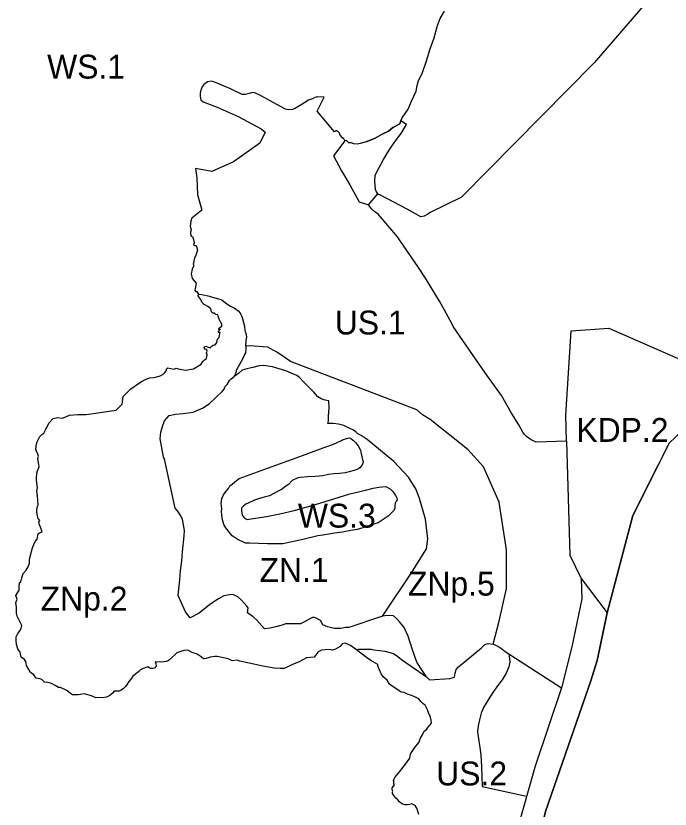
# Model space of a CAD drawing. Extents: x 7421614 to 7422630, y 5544623 to 5545754.
# Drawn here: x 7421918.2 to 7422192.7, y 5544838.1 to 5545170.9 of the extents above; entities that cross this region are included whole.
import ezdxf

# ---------------------------------------------------------------- set-up
doc = ezdxf.new("R2010")
doc.units = 0
for name, color, linetype in [('LIN_Granica Planu', 7, 'Continuous'), ('LIN_Linia Zabudowy Nieprzekraczalna', 7, 'Continuous'), ('LIN_Linie Rozgraniczajace', 7, 'Continuous'), ('TXT_Oznaczenia Przeznaczenia', 7, 'Continuous')]:
    doc.layers.add(name, color=color, linetype=linetype)

msp = doc.modelspace()

# ---------------------------------------------------------------- linework, layer by layer
at = {"layer": 'LIN_Granica Planu'}
for points in [[(7422208.14, 5545006.76), (7422192.24, 5544991.56), (7422177, 5544961.18), (7422166.21, 5544920.42)], [(7422166.21, 5544920.42), (7422162.02, 5544900.44), (7422159.37, 5544891.82), (7422140.37, 5544837.11), (7422136.08, 5544819.42), (7422134.53, 5544813.25), (7422129.23, 5544788.52), (7422123.65, 5544775.25), (7422118.35, 5544765.76), (7422111.44, 5544749.36), (7422109.16, 5544743.94), (7422108.81, 5544743.12)]]:
    msp.add_lwpolyline(points, dxfattribs=at)
at = {"layer": 'LIN_Linia Zabudowy Nieprzekraczalna'}
for p, q in [((7422079.22, 5545125.61), (7422076.29, 5545124.01)), ((7422079.75, 5545126.84), (7422079.22, 5545125.61)), ((7422074.45, 5545122.44), (7422071.78, 5545121.21)), ((7422076.29, 5545124.01), (7422074.45, 5545122.44)), ((7422056.19, 5545118.39), (7422051.48, 5545112.08)), ((7422068.85, 5545119.56), (7422065.13, 5545118.08)), ((7422071.78, 5545121.21), (7422068.85, 5545119.56)), ((7422066.17, 5545091.62), (7422070, 5545096.25)), ((7422062.26, 5545092.78), (7422066.17, 5545091.62))]:
    msp.add_line(p, q, dxfattribs=at)
for points in [[(7422070, 5545096.25), (7422069.43, 5545097.07), (7422069.11, 5545098.01), (7422068.71, 5545101.51), (7422068.97, 5545103.93), (7422069.56, 5545105.38), (7422072.39, 5545110.56), (7422074.1, 5545113.36), (7422075.3, 5545115.32), (7422077.49, 5545118.45), (7422079.84, 5545121.47), (7422082.09, 5545125.28), (7422079.75, 5545126.84)], [(7422065.13, 5545118.08), (7422062.61, 5545117.36), (7422061.5, 5545117.05), (7422060.03, 5545117.18), (7422058.87, 5545117.54), (7422057.88, 5545117.63), (7422056.82, 5545118.5), (7422056.19, 5545118.39)], [(7422051.48, 5545112.08), (7422054.82, 5545105.91), (7422058.35, 5545100), (7422062.26, 5545092.78)], [(7422124.98, 5544903.28), (7422125.37, 5544899.8), (7422124.97, 5544897.74), (7422123.82, 5544895.04), (7422122.14, 5544892.32), (7422120.59, 5544890.28), (7422118.51, 5544887.46), (7422117.06, 5544885.07), (7422114.4, 5544880.74), (7422113.44, 5544878.34), (7422112.62, 5544875.45), (7422112.07, 5544873.02), (7422111.88, 5544870.57), (7422112.09, 5544868.49), (7422112.78, 5544863.94), (7422113.24, 5544860.86), (7422113.53, 5544855.99), (7422113.74, 5544847.6), (7422132.46, 5544843.53)]]:
    msp.add_lwpolyline(points, dxfattribs=at)
at = {"layer": 'LIN_Linie Rozgraniczajace'}
for p, q in [((7422155.33, 5544934.86), (7422166.21, 5544920.42)), ((7422071.09, 5544918.7), (7422072.02, 5544918.95))]:
    msp.add_line(p, q, dxfattribs=at)
for points in [[(7422247.74, 5545302.11), (7422251.81, 5545292.57), (7422253.78, 5545282.38), (7422253.25, 5545272.02), (7422246.41, 5545262.11), (7422217.9, 5545236.43), (7422182.85, 5545176.71), (7422160.75, 5545151.12), (7422105.13, 5545094.82), (7422092.03, 5545088.33), (7422090.99, 5545087.63), (7422089.52, 5545086.84), (7422088.09, 5545086.6), (7422082.36, 5545089.7), (7422070.87, 5545095.79), (7422070, 5545096.25)], [(7422080.29, 5545128.07), (7422082.74, 5545131.73), (7422084.09, 5545135.14), (7422086.1, 5545139.3), (7422086.58, 5545141.7), (7422087.1, 5545143.77), (7422088.63, 5545146.68), (7422090.38, 5545151.56), (7422091.96, 5545156.97), (7422093.66, 5545161.66), (7422094.86, 5545166.45), (7422096.25, 5545169.76), (7422098.02, 5545172.85)], [(7422065.13, 5545118.08), (7422062.61, 5545117.36), (7422061.5, 5545117.05), (7422060.03, 5545117.18), (7422058.87, 5545117.54), (7422057.88, 5545117.63), (7422056.82, 5545118.5), (7422056.19, 5545118.39), (7422055.75, 5545119.31), (7422055.27, 5545119.74), (7422054.24, 5545120.84), (7422054.01, 5545121.66), (7422053.42, 5545122.18), (7422052.75, 5545122.65), (7422052.68, 5545122.73), (7422051.83, 5545122.15), (7422044.51, 5545130.94), (7422047.5, 5545136.72), (7422044.8, 5545136.91), (7422044.43, 5545136.75), (7422044.15, 5545136.74), (7422043.59, 5545136.63), (7422042.57, 5545136.08), (7422040.95, 5545135.5), (7422037.89, 5545133.5), (7422035.09, 5545131.87), (7422034.25, 5545131.59), (7422032.55, 5545131.4), (7422031.25, 5545131.71), (7422024.63, 5545135.31), (7422022.58, 5545136.46), (7422020.27, 5545137.66), (7422019.27, 5545138.21), (7422018.39, 5545138.57), (7422017.5, 5545138.68), (7422016.02, 5545138.32), (7422014.32, 5545137.81), (7422013.05, 5545137.85), (7422007.91, 5545140.35), (7422001.29, 5545143.24), (7422000.24, 5545143.5), (7421998.73, 5545143.12), (7421997.2, 5545142.19), (7421996.32, 5545141.04), (7421995.77, 5545139.75), (7421995.42, 5545138.46), (7421995.48, 5545136.96), (7421995.82, 5545135.62), (7421996.69, 5545134.81), (7422002.69, 5545132.49), (7422011.37, 5545128.68), (7422021.07, 5545123.48), (7422022.81, 5545122), (7422020.59, 5545117.39), (7422009.53, 5545109.65), (7422000.42, 5545105.58), (7421993.48, 5545106.8), (7421993.62, 5545105.84), (7421994.07, 5545102.87), (7421994.39, 5545095.94), (7421996.21, 5545089.35), (7421992.72, 5545086.5), (7421992.01, 5545085.92), (7421991.58, 5545084.82), (7421991.37, 5545083.67), (7421991.33, 5545082.65), (7421991.76, 5545081.08), (7421991.47, 5545080.17), (7421991.42, 5545079.37), (7421991.78, 5545078.48), (7421992.25, 5545078.24), (7421992.69, 5545077.03), (7421992.95, 5545075.67), (7421992.68, 5545074.93), (7421993.29, 5545074.47), (7421993.76, 5545074.52), (7421993.98, 5545074.03), (7421994.36, 5545072.54), (7421993.61, 5545070.44), (7421993.11, 5545069.18), (7421992.51, 5545066.64), (7421992.77, 5545066.16), (7421992.1, 5545064.59), (7421991.67, 5545062.61), (7421992.13, 5545060.7), (7421993.86, 5545058.68), (7421993.53, 5545057.03), (7421993.19, 5545055.79), (7421993.7, 5545055.12), (7421994, 5545055.37), (7421994.75, 5545054.14)], [(7422079.75, 5545126.84), (7422080.29, 5545128.07)], [(7422070, 5545096.25), (7422069.43, 5545097.07), (7422069.11, 5545098.01), (7422068.71, 5545101.51), (7422068.97, 5545103.93), (7422069.56, 5545105.38), (7422072.39, 5545110.56), (7422074.1, 5545113.36), (7422075.3, 5545115.32), (7422077.49, 5545118.45), (7422079.84, 5545121.47), (7422082.09, 5545125.28), (7422079.75, 5545126.84)], [(7422076.29, 5545124.01), (7422079.22, 5545125.61)], [(7422079.22, 5545125.61), (7422079.75, 5545126.84)], [(7422071.78, 5545121.21), (7422074.45, 5545122.44)], [(7422074.45, 5545122.44), (7422076.29, 5545124.01)], [(7422065.13, 5545118.08), (7422068.85, 5545119.56)], [(7422068.85, 5545119.56), (7422071.78, 5545121.21)], [(7422149.25, 5544992.43), (7422136.41, 5544992.07), (7422134.42, 5544992.99), (7422132.41, 5544994.44), (7422131.61, 5544995.27), (7422130.8, 5544996.2), (7422129.25, 5544999.3), (7422126.13, 5545004.12), (7422121.88, 5545011.57), (7422115, 5545021.11), (7422106.96, 5545032.85), (7422101.65, 5545040.58), (7422101.51, 5545040.82), (7422101.14, 5545041.85), (7422098.07, 5545047.34), (7422095.84, 5545051.15), (7422092, 5545057.53), (7422090.01, 5545060.83), (7422086.76, 5545065.72), (7422081.01, 5545074.23), (7422078.29, 5545078.1), (7422071.82, 5545085.72), (7422070.11, 5545087.66), (7422068.73, 5545088.64), (7422067.38, 5545089.95), (7422066.17, 5545091.62), (7422070, 5545096.25)], [(7422061.03, 5544904.84), (7422058.6, 5544906.67), (7422056.35, 5544907.7), (7422055.07, 5544907.36), (7422054.2, 5544906.26), (7422052.23, 5544905.19), (7422051.02, 5544904.79), (7422049.65, 5544905.06), (7422046.41, 5544904.79), (7422045.01, 5544904.03), (7422043.31, 5544901.78), (7422040.05, 5544901.53), (7422036.99, 5544899.83), (7422034.01, 5544898.62), (7422030.77, 5544897.05), (7422029.08, 5544896.99), (7422026.52, 5544897.21), (7422021.8, 5544898.01), (7422017.96, 5544898.9), (7422012.07, 5544900.11), (7422010.96, 5544900.53), (7422008.96, 5544900.29), (7422007.23, 5544901.04), (7422002.65, 5544902.08), (7422001.58, 5544902.14), (7421999.67, 5544901.74), (7421997.95, 5544901.31), (7421996.9, 5544901.17), (7421995.92, 5544902), (7421994.25, 5544903.05), (7421992.11, 5544903.83), (7421990.28, 5544904.7), (7421988.58, 5544904.58), (7421986.5, 5544903.96), (7421985.75, 5544903.65), (7421982.77, 5544900.8), (7421982.01, 5544900.28), (7421981.26, 5544900), (7421980.2, 5544899.82), (7421978.8, 5544899.7), (7421976.63, 5544899.88), (7421976.95, 5544899.09), (7421976.96, 5544898.03), (7421976.36, 5544897.24), (7421975.66, 5544897.04), (7421974.79, 5544897.04), (7421974.11, 5544897.36), (7421973.49, 5544897.79), (7421971.6, 5544897.03), (7421970.49, 5544896.48), (7421969.55, 5544895.62), (7421967.27, 5544893.8), (7421966.56, 5544892.66), (7421965.6, 5544891.63), (7421964.88, 5544890.53), (7421964.15, 5544889.55), (7421963.28, 5544888.64), (7421962.26, 5544887.77), (7421961.35, 5544887.54), (7421959.47, 5544887.61), (7421958.54, 5544886.56), (7421957.53, 5544885.71), (7421956.25, 5544885.08), (7421954.39, 5544884.79), (7421953.03, 5544884.83), (7421951.74, 5544884.71), (7421949.95, 5544885.59), (7421948.4, 5544886.06), (7421946.85, 5544886.38), (7421944.49, 5544886.05), (7421941.9, 5544886.06), (7421941.07, 5544886.51), (7421939.48, 5544887.84), (7421936.92, 5544889.11), (7421936, 5544889.04), (7421934.71, 5544889.9), (7421933.15, 5544890.78), (7421931.75, 5544891.21), (7421930.18, 5544891.26), (7421928.99, 5544892.45), (7421928.22, 5544892.74), (7421926.7, 5544893.04), (7421925.71, 5544894.44), (7421924.35, 5544895.32), (7421923.67, 5544896.63), (7421922.58, 5544898.25), (7421922.32, 5544900.04), (7421921.74, 5544900.78), (7421920.39, 5544901.79), (7421920.17, 5544903.01), (7421919.94, 5544903.87), (7421918.94, 5544905.25), (7421918.42, 5544907.13), (7421918.29, 5544908.76), (7421918.27, 5544910.34), (7421919.04, 5544911.69), (7421919.98, 5544912.99), (7421920.38, 5544913.96), (7421920.7, 5544915.07), (7421919.6, 5544917.39), (7421918.66, 5544919.01), (7421918.4, 5544920.26), (7421918.48, 5544922.75), (7421918.19, 5544924.6), (7421918.74, 5544926.16), (7421918.16, 5544927.72), (7421919.58, 5544929.93), (7421919.48, 5544931.46), (7421919.69, 5544932.95), (7421920.22, 5544933.46), (7421920.68, 5544935.15), (7421921.28, 5544936.96), (7421922.49, 5544938.37), (7421923.38, 5544939.75), (7421923.83, 5544941.27), (7421923.92, 5544942.69), (7421924.19, 5544943.98), (7421925.19, 5544947.64), (7421925.71, 5544949.1), (7421926.33, 5544950.27), (7421927.05, 5544951.37), (7421927.57, 5544953.57), (7421928.08, 5544953.95), (7421929.13, 5544954.33), (7421928.5, 5544956.4), (7421928.01, 5544957.35), (7421927.84, 5544958.39), (7421928.26, 5544959.09), (7421927.58, 5544960.04), (7421927.09, 5544961.72), (7421926.9, 5544962.92), (7421927.11, 5544964.8), (7421927.55, 5544965.53), (7421927.44, 5544967.47), (7421927.2, 5544969.43), (7421927.02, 5544971.43), (7421927.23, 5544972.91), (7421926.93, 5544974.8), (7421926.79, 5544976.37), (7421926.85, 5544977.42), (7421926.99, 5544978.33), (7421926.95, 5544979.05), (7421927.21, 5544980.03), (7421927.93, 5544981.71), (7421927.83, 5544982.5), (7421927.37, 5544985.19), (7421927.59, 5544986.07), (7421927.36, 5544986.97), (7421926.85, 5544988.24), (7421926.6, 5544989.07), (7421926.64, 5544990.29), (7421926.8, 5544991.33), (7421927.03, 5544992.21), (7421928.18, 5544994.37), (7421929.01, 5544995.28), (7421929.85, 5544995.81), (7421930.78, 5544997.48), (7421931.04, 5544997.83), (7421931.99, 5544999.92), (7421933.87, 5545001.88), (7421935.7, 5545002.35), (7421937.69, 5545002.05), (7421940.7, 5545003.32), (7421944.18, 5545003.66), (7421947.62, 5545003.57), (7421960.27, 5545005.41), (7421962.74, 5545007.95), (7421963.12, 5545011.19), (7421964.23, 5545012.08), (7421965.08, 5545013.11), (7421966.45, 5545014.34), (7421969.68, 5545016.65), (7421971.12, 5545017.6), (7421972.54, 5545018.36), (7421974.25, 5545018.93), (7421975.91, 5545019.1), (7421977.34, 5545019.41), (7421978.75, 5545019.81), (7421980.02, 5545020.49), (7421980.69, 5545021.23), (7421981.25, 5545021.97), (7421981.53, 5545022.93), (7421981.95, 5545023.2), (7421983.12, 5545022.9), (7421984.52, 5545022.68), (7421985.39, 5545023.01), (7421986.2, 5545022.73), (7421989.49, 5545022.2), (7421992.64, 5545022.74), (7421995.86, 5545024.79), (7421996.58, 5545025.79), (7421997.3, 5545026.51), (7421998.15, 5545027.15), (7421998.48, 5545028.47), (7421998.12, 5545029.44), (7421998.38, 5545030.18), (7421998.16, 5545031), (7421997.6, 5545030.88), (7421996.96, 5545031.4), (7421997.63, 5545032.09), (7421998.08, 5545032.3), (7421998.37, 5545032.01), (7421999.77, 5545031.58), (7422000.13, 5545032.11), (7422000.9, 5545032.7), (7422001.83, 5545032.91), (7422002.31, 5545033.6), (7422002.69, 5545034.49), (7422002.75, 5545035.2), (7422003.45, 5545035.99), (7422003.59, 5545036.9), (7422003.92, 5545038.07), (7422003.3, 5545038.07), (7422003.11, 5545038.4), (7422003.58, 5545039.02), (7422003.96, 5545039.43), (7422003.29, 5545039.32), (7422003.28, 5545039.69), (7422003.84, 5545040.29), (7422004.54, 5545040.74), (7422004.57, 5545041.56), (7422003.99, 5545042.54), (7422003.42, 5545043.66), (7422003.01, 5545044.92), (7422002.97, 5545045.49), (7422002.12, 5545045.58), (7422001.53, 5545046.06), (7422000.86, 5545046.13), (7422000.27, 5545046.72), (7421999.98, 5545047.92), (7421998.72, 5545048.97), (7421997.21, 5545049.78), (7421996.21, 5545050.79), (7421995.75, 5545051.87), (7421994.98, 5545053.03), (7421994.6, 5545053.45), (7421994.75, 5545054.14)], [(7421994.75, 5545054.14), (7421996.21, 5545053.9), (7421998.75, 5545053.37), (7422001.26, 5545052.74), (7422004.59, 5545051.68), (7422006.07, 5545050.49), (7422007.87, 5545049.16), (7422009.86, 5545048.16), (7422011.37, 5545047.13), (7422012.48, 5545046.01)], [(7422012.89, 5545045.21), (7422012.48, 5545046.01)], [(7422013.32, 5545044.11), (7422012.89, 5545045.2)], [(7422012.89, 5545045.2), (7422012.89, 5545045.21)], [(7422013.84, 5545042.04), (7422013.32, 5545044.11)], [(7422014.61, 5545032.34), (7422014.75, 5545034.71), (7422015.06, 5545036.13), (7422014.94, 5545037.09), (7422014.57, 5545038.24), (7422014.3, 5545038.85), (7422014.19, 5545040.49), (7422013.84, 5545042.04)], [(7422149.25, 5544992.43), (7422148.95, 5545003.27), (7422151.09, 5545038.77), (7422166.95, 5545039.87), (7422197.24, 5545026.57), (7422205.48, 5545011.59)], [(7422014.61, 5545032.34), (7422014.62, 5545031.5), (7422014.63, 5545030.66), (7422014.55, 5545030.05), (7422014.48, 5545029.45), (7422014.12, 5545028.73), (7422013.76, 5545028.01), (7422012.67, 5545025.82), (7422010.73, 5545022.35)], [(7422118.46, 5544907.31), (7422120.99, 5544916.94), (7422124.05, 5544930.62), (7422124.07, 5544946.78), (7422121, 5544966.87), (7422114.31, 5544981.65), (7422107.84, 5544988.92), (7422091.94, 5545001.5), (7422088.72, 5545003.51), (7422086.35, 5545005.55), (7422033.38, 5545025.83), (7422030.53, 5545027.77), (7422027.89, 5545029.57), (7422025.8, 5545030.81), (7422023.85, 5545031.87), (7422016.16, 5545032.41), (7422014.61, 5545032.34)], [(7422072.02, 5544918.95), (7422083.88, 5544936.76), (7422090.47, 5544947.27), (7422091.04, 5544951.42), (7422089.99, 5544959.69), (7422087.48, 5544968.42), (7422086.09, 5544972.22), (7422082.91, 5544977.28), (7422076.79, 5544983.83), (7422065.6, 5544993.11), (7422063.05, 5544994.78), (7422061.65, 5544995.46), (7422060.93, 5544996.16), (7422059.84, 5544997), (7422057.97, 5544997.92), (7422055.81, 5544998.96), (7422053.51, 5544999.63), (7422051.47, 5544999.79), (7422049.09, 5544999.8), (7422049.37, 5545000.98), (7422049.28, 5545003.1), (7422049.63, 5545006.33), (7422049.43, 5545009.41), (7422048, 5545009.63), (7422046.3, 5545010.25), (7422044.85, 5545011.07), (7422043.14, 5545013.01), (7422038.99, 5545017.13), (7422037.22, 5545019.08), (7422036.08, 5545019.96), (7422033.6, 5545020.99), (7422031.37, 5545021.98), (7422028.61, 5545022.75), (7422025.85, 5545023.56), (7422022.09, 5545024.13), (7422020.19, 5545023.97), (7422017.65, 5545023.39), (7422015.11, 5545022.76), (7422013.14, 5545022.24), (7422011.55, 5545020.88), (7422009.69, 5545019.56)], [(7422010.55, 5545021.48), (7422010.45, 5545021.2)], [(7422010.64, 5545021.92), (7422010.55, 5545021.48)], [(7422010.73, 5545022.35), (7422010.64, 5545021.92)], [(7422071.09, 5544918.7), (7422057.83, 5544914.21), (7422056.47, 5544914.3), (7422054.49, 5544913.77), (7422051.69, 5544913.78), (7422048.86, 5544914.53), (7422046.98, 5544915.31), (7422045.96, 5544917.2), (7422044.2, 5544918.22), (7422042.95, 5544918.57), (7422041.5, 5544917.96), (7422039.02, 5544916.56), (7422037.57, 5544915.74), (7422032.17, 5544915.79), (7422031.26, 5544915.75), (7422030.26, 5544915.34), (7422027.82, 5544914.65), (7422024.83, 5544914), (7422022.44, 5544913.71), (7422019.25, 5544917.34), (7422017.74, 5544918.76), (7422015.28, 5544920.38), (7422015.64, 5544922.56), (7422015.11, 5544923.15), (7422012.84, 5544925.68), (7422011.29, 5544927.13), (7422010.22, 5544927.74), (7422009.03, 5544928.1), (7422007.8, 5544928.02), (7422005.36, 5544927.54), (7422003.23, 5544926.25), (7421999.94, 5544924.24), (7421997.3, 5544922.13), (7421995.01, 5544920.3), (7421991.35, 5544918.3), (7421989.28, 5544920.82), (7421986.26, 5544927.63), (7421987.01, 5544934.24), (7421987.17, 5544938.22), (7421987.75, 5544942.1), (7421988.12, 5544945.97), (7421988.78, 5544952.74), (7421988.89, 5544954.88), (7421988.01, 5544959.67), (7421987.12, 5544961.56), (7421986, 5544963.16), (7421985.01, 5544964.32), (7421980.6, 5544984.38), (7421980.6, 5544984.38), (7421980.05, 5544985.85), (7421978.65, 5544993.34), (7421978.98, 5544996.22), (7421979.62, 5544998.57), (7421980.5, 5545000.94), (7421982.44, 5545003.26), (7421985.15, 5545003.69), (7421988.39, 5545003.98), (7421992.61, 5545004.63), (7421994.81, 5545005.52), (7421996.77, 5545006.48), (7421999.38, 5545008.27), (7422004.74, 5545013.26), (7422005.51, 5545014.29), (7422005.84, 5545015.23), (7422006.77, 5545016.23), (7422007.73, 5545017.83), (7422008.43, 5545018.58), (7422009.69, 5545019.56)], [(7422009.9, 5545019.91), (7422009.69, 5545019.56)], [(7422010.11, 5545020.26), (7422009.9, 5545019.91)], [(7422010.23, 5545020.59), (7422010.11, 5545020.26)], [(7422010.33, 5545020.87), (7422010.23, 5545020.59)], [(7422010.45, 5545021.2), (7422010.33, 5545020.87)], [(7422166.21, 5544920.42), (7422177, 5544961.18), (7422187.77, 5544982.66), (7422192.24, 5544991.56), (7422208.14, 5545006.76)], [(7422071.84, 5544959.23), (7422070.19, 5544958.16), (7422068.37, 5544957.54), (7422067.14, 5544956.98), (7422064.83, 5544956.32), (7422062.72, 5544955.78), (7422061.34, 5544955.32), (7422058.67, 5544954.91), (7422055.26, 5544954.27), (7422051.92, 5544953.83), (7422049.51, 5544953.45), (7422046.93, 5544952.94), (7422044.82, 5544952.78), (7422038.62, 5544951.24), (7422030.16, 5544949.41), (7422023.74, 5544949.31), (7422016.12, 5544949.61), (7422014.51, 5544949.61), (7422010.95, 5544951.31), (7422008.94, 5544952.72), (7422006.24, 5544956.06), (7422005.37, 5544957.46), (7422004.8, 5544959.49), (7422004.64, 5544961.41), (7422004.46, 5544963), (7422004.58, 5544964.09), (7422004.25, 5544966.21), (7422004.6, 5544968.43), (7422005.23, 5544969.94), (7422006.35, 5544971.47), (7422007.44, 5544972.6), (7422007.93, 5544973.67), (7422008.96, 5544974.39), (7422010.1, 5544975.36), (7422011.79, 5544976.71), (7422014.98, 5544977.92), (7422025.64, 5544981.77), (7422028.78, 5544982.91), (7422037.34, 5544986.02), (7422047.1, 5544989.59), (7422051.45, 5544991.11), (7422054.73, 5544992.65), (7422055.51, 5544993.16), (7422057.94, 5544993.78), (7422058.57, 5544993.71), (7422059.25, 5544993.11), (7422059.81, 5544992.71), (7422060.7, 5544991.89), (7422061.77, 5544990.54), (7422062.74, 5544988.7), (7422062.94, 5544987.76), (7422063.63, 5544984.65), (7422063.93, 5544983.92), (7422063.79, 5544983.2), (7422063.34, 5544982.25), (7422062.49, 5544981.27), (7422061.58, 5544980.74), (7422060.14, 5544980.13), (7422058.05, 5544979.55), (7422056.37, 5544979.16), (7422054.01, 5544978.86), (7422051.7, 5544978.69), (7422049.37, 5544978.41), (7422046.97, 5544977.92), (7422043.93, 5544977.65), (7422040.6, 5544977.46), (7422037.38, 5544977.21), (7422036.41, 5544977.04), (7422034.07, 5544975.87), (7422032.53, 5544974.18), (7422031.08, 5544973.26), (7422029.96, 5544972.31), (7422027.93, 5544971.25), (7422024.53, 5544969.52), (7422022.31, 5544968.94), (7422019.92, 5544968.3), (7422018.27, 5544967.71), (7422015.58, 5544966.42), (7422014.66, 5544965.96), (7422013.64, 5544965.19), (7422012.82, 5544964.36), (7422012.83, 5544963.15), (7422013.18, 5544961.44), (7422014.09, 5544960.15), (7422015.16, 5544959.63), (7422015.85, 5544959.73), (7422023.27, 5544960.81), (7422028.95, 5544961.94), (7422034.96, 5544963.35), (7422043.9, 5544965.88), (7422051.63, 5544968.17), (7422058.23, 5544970.33), (7422064.84, 5544971.82), (7422068.12, 5544972.78), (7422070.46, 5544973.19), (7422073.4, 5544973.39), (7422075.16, 5544972.41), (7422076.29, 5544971.28), (7422077.45, 5544969.6), (7422078.02, 5544968.63), (7422078.16, 5544967.84), (7422077.69, 5544967.24), (7422077.32, 5544966.42), (7422077.16, 5544965.33), (7422077.15, 5544964.2), (7422076.67, 5544963.24), (7422074.35, 5544961.02), (7422071.84, 5544959.23)], [(7422149.25, 5544992.43), (7422150.58, 5544944.54), (7422155.33, 5544934.86)], [(7422155.33, 5544934.86), (7422155.68, 5544926.24), (7422151.45, 5544906.09), (7422147.03, 5544888.89)], [(7422090.51, 5544893.5), (7422088.72, 5544896.12), (7422086.45, 5544899.76), (7422084.54, 5544904.9), (7422082.71, 5544910.56), (7422081.06, 5544914.23), (7422079.3, 5544916.52), (7422077.89, 5544918.04), (7422076.6, 5544919.16), (7422075.05, 5544919.3), (7422072.94, 5544919.21), (7422072.02, 5544918.95)], [(7422081.44, 5544710.61), (7422086.01, 5544708.77), (7422091.86, 5544706.43), (7422092.66, 5544706.11), (7422094.41, 5544710.72), (7422094.71, 5544711.38), (7422100.83, 5544724.83), (7422103.93, 5544731.63), (7422104.27, 5544732.43), (7422108.81, 5544743.12), (7422109.16, 5544743.94), (7422111.44, 5544749.36), (7422118.35, 5544765.76), (7422123.65, 5544775.25), (7422129.23, 5544788.52), (7422134.53, 5544813.25), (7422136.08, 5544819.42), (7422137.46, 5544825.1), (7422140.37, 5544837.11), (7422159.37, 5544891.82), (7422162.02, 5544900.44), (7422166.21, 5544920.42)], [(7422061.03, 5544904.84), (7422061.99, 5544905.1), (7422067.27, 5544905.22), (7422068.34, 5544904.84), (7422073.14, 5544904.29), (7422076.65, 5544903.4), (7422078.38, 5544902.04), (7422079.91, 5544900.83), (7422083.65, 5544898.25), (7422090.51, 5544893.5)], [(7422090.51, 5544893.5), (7422091.65, 5544892.25), (7422100.29, 5544892.92), (7422102.2, 5544893.44), (7422102.44, 5544895.08), (7422102.96, 5544896.65), (7422103.87, 5544897.74), (7422113.53, 5544905.71), (7422114.92, 5544907.11), (7422116.26, 5544907.48), (7422118.46, 5544907.31)], [(7422118.46, 5544907.31), (7422120.31, 5544906.38), (7422122.09, 5544905.33), (7422123.52, 5544904.23), (7422147.03, 5544888.89)], [(7422087.28, 5544835.8), (7422086.36, 5544838.46), (7422085.77, 5544839.27), (7422085.1, 5544839.89), (7422084.33, 5544840.32), (7422083.31, 5544839.99), (7422082.27, 5544839.86), (7422081.3, 5544839.9), (7422080.14, 5544840.29), (7422079.09, 5544841.08), (7422078.42, 5544841.99), (7422077.6, 5544842.64), (7422076.84, 5544843.58), (7422076.24, 5544844.62), (7422076.14, 5544845.27), (7422076.31, 5544845.54), (7422076.01, 5544846.21), (7422076.09, 5544846.91), (7422076.45, 5544847.52), (7422077.05, 5544848.27), (7422076.75, 5544848.7), (7422076.69, 5544849.3), (7422076.84, 5544849.59), (7422076.66, 5544850.08), (7422076.84, 5544850.71), (7422077.15, 5544851.36), (7422079.32, 5544853.91), (7422080.15, 5544855.01), (7422081.27, 5544856.35), (7422082.4, 5544857.86), (7422083.44, 5544859.48), (7422083.8, 5544861.18), (7422085.2, 5544863.37), (7422086.17, 5544864.57), (7422087.18, 5544866), (7422087.99, 5544867.76), (7422088.77, 5544869.18), (7422089.54, 5544870.74), (7422090.59, 5544871.6), (7422091.06, 5544872.33), (7422091.89, 5544873.24), (7422092.5, 5544874.09), (7422092.45, 5544875.33), (7422092.08, 5544876.59), (7422091.37, 5544878.18), (7422090.86, 5544879.77), (7422089.88, 5544881.63), (7422089.07, 5544882.2), (7422088.17, 5544883.1), (7422087.21, 5544884.29), (7422086.12, 5544884.89), (7422084.1, 5544885.79), (7422082.48, 5544886.32), (7422081.1, 5544886.95), (7422079.88, 5544887.18), (7422078.47, 5544888.17), (7422076.46, 5544889.38), (7422074.98, 5544890.46), (7422073.92, 5544892.17), (7422072.3, 5544893.56), (7422071.49, 5544894.76), (7422070.07, 5544898.16), (7422070.06, 5544898.78), (7422067.14, 5544900.43), (7422065.32, 5544901.62), (7422061.03, 5544904.84)], [(7422147.03, 5544888.89), (7422136.01, 5544856.12), (7422128.91, 5544830.94), (7422121.52, 5544809.87), (7422115.38, 5544791.06), (7422087.21, 5544733.94), (7422083.31, 5544723.39), (7422081.85, 5544714.99), (7422081.44, 5544710.61)]]:
    msp.add_lwpolyline(points, dxfattribs=at)

# ---------------------------------------------------------------- texts
at = {"layer": 'TXT_Oznaczenia Przeznaczenia'}
for s, p in [('WS.1', (7421931.28, 5545144.55)), ('US.1', (7422051.97, 5545037.19)), ('KDP.2', (7422153.33, 5544992.14)), ('WS.3', (7422036.48, 5544956.17)), ('ZN.1', (7422020.39, 5544933.4)), ('ZNp.5', (7422082.67, 5544927.63)), ('ZNp.2', (7421928.57, 5544921.38)), ('US.2', (7422094.53, 5544848.01))]:
    msp.add_text(s, height=10, dxfattribs=at).set_placement(p)

doc.saveas('drawing.dxf')
